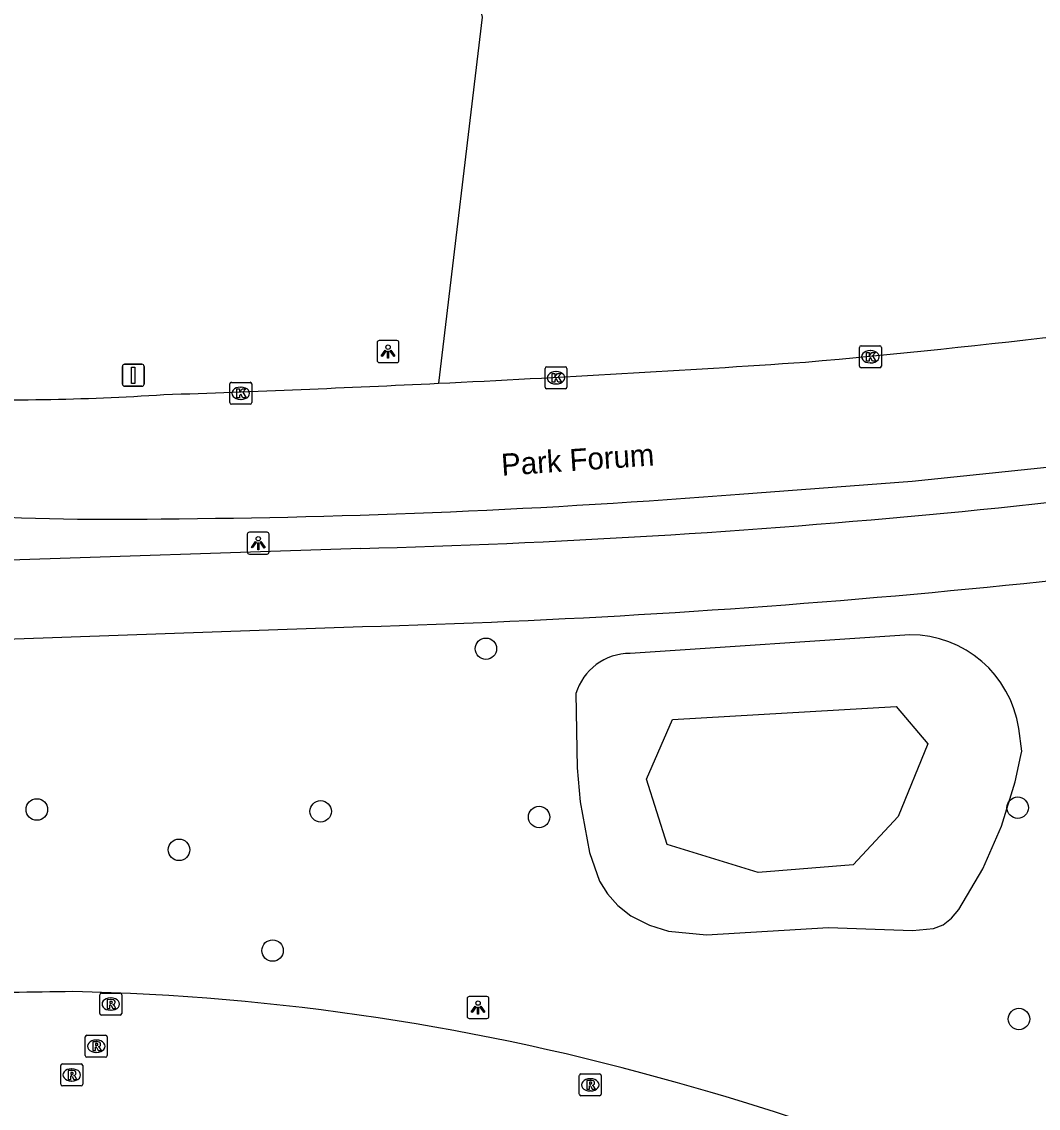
# Model space of a CAD drawing. Extents: x 154324 to 155743, y 382939 to 384183.
# Drawn here: x 155304.56 to 155350.9, y 383470.22 to 383519.75 of the extents above; entities that cross this region are included whole.
import ezdxf

# ---------------------------------------------------------------- set-up
doc = ezdxf.new("R2010")
doc.units = 0
for name, color, linetype in [('IMGEO_Berm_groen', 7, 'Continuous'), ('IMGEO_Boom', 7, 'Continuous'), ('IMGEO_Fietspad_gesloten', 7, 'Continuous'), ('IMGEO_Groenvoorziening', 7, 'Continuous'), ('IMGEO_Kolk', 7, 'Continuous'), ('IMGEO_Lichtpunt', 7, 'Continuous'), ('IMGEO_Meer_plas_ven_vijver', 7, 'Continuous'), ('IMGEO_Openbare_ruimte_label', 7, 'Continuous'), ('IMGEO_Rijbaan_lokaal_gesloten', 7, 'Continuous'), ('IMGEO_Rijbaan_lokaal_open', 7, 'Continuous'), ('IMGEO_Rioolput', 7, 'Continuous'), ('IMGEO_Verkeersbordpaal', 7, 'Continuous')]:
    doc.layers.add(name, color=color, linetype=linetype)

msp = doc.modelspace()

# ---------------------------------------------------------------- linework, layer by layer
at = {"layer": 'IMGEO_Berm_groen'}
msp.add_lwpolyline([(155249.962, 383983.402), (155261.74, 383912.135), (155306.103, 383602.506), (155325.548, 383519.946), (155323.557, 383503.266)], dxfattribs=at)
at = {"layer": 'IMGEO_Boom'}
for centre in [(155325.724, 383491.168), (155305.253, 383483.841), (155318.191, 383483.757), (155349.966, 383483.923), (155328.148, 383483.498), (155311.734, 383482.003), (155315.999, 383477.412), (155350.024, 383474.291)]:
    msp.add_circle(centre, 0.489, dxfattribs=at)
at = {"layer": 'IMGEO_Fietspad_gesloten'}
for points in [[(155320.016, 383495.74), (155302.646, 383495.154), (155298.319, 383495.134), (155298.615, 383497.439)], [(155299.822, 383491.37), (155302.096, 383491.551), (155320.102, 383492.177)]]:
    msp.add_lwpolyline(points, dxfattribs=at)
for centre, radius, start, end in [((155310.263, 383877.333), 381.717, 271.46401, 279.46134), ((155308.945, 383894.859), 402.836, 271.58712, 279.22715)]:
    msp.add_arc(centre, radius, start, end, dxfattribs=at)
at = {"layer": 'IMGEO_Groenvoorziening'}
for points in [[(155345.053, 383491.808), (155332.293, 383490.958)], [(155329.827, 383489.121), (155329.88, 383485.737), (155330.021, 383484.191), (155330.45, 383481.888), (155330.906, 383480.582), (155331.267, 383479.991), (155331.738, 383479.46), (155332.334, 383479.002), (155333.186, 383478.567), (155334.045, 383478.3), (155335.78, 383478.124), (155341.334, 383478.467), (155345.17, 383478.319), (155346.128, 383478.422), (155346.575, 383478.592), (155346.952, 383478.891), (155347.276, 383479.28), (155348.376, 383481.137)], [(155348.376, 383481.137), (155349.221, 383483.087), (155349.842, 383485.097), (155350.114, 383486.303), (155350.16, 383486.506), (155350.011, 383487.539)]]:
    msp.add_lwpolyline(points, dxfattribs=at)
for centre, radius, start, end in [((155345.053, 383486.794), 5.014, 8.5403, 90.0007), ((155332.295, 383488.382), 2.576, 90.0351, 163.332)]:
    msp.add_arc(centre, radius, start, end, dxfattribs=at)
at = {"layer": 'IMGEO_Kolk'}
for p, q in [((155342.749, 383504.05), (155342.749, 383504.902)), ((155342.824, 383504.976), (155343.676, 383504.976)), ((155343.237, 383504.756), (155343.262, 383504.756)), ((155343.75, 383504.902), (155343.75, 383504.05)), ((155328.493, 383504.017), (155329.345, 383504.017)), ((155343.26, 383504.196), (155343.235, 383504.196)), ((155328.418, 383503.091), (155328.418, 383503.943)), ((155328.906, 383503.797), (155328.931, 383503.797)), ((155329.419, 383503.943), (155329.419, 383503.091)), ((155343.676, 383503.976), (155342.824, 383503.976)), ((155314.049, 383502.384), (155314.049, 383503.236)), ((155314.124, 383503.31), (155314.976, 383503.31)), ((155314.537, 383503.09), (155314.562, 383503.09)), ((155315.05, 383503.236), (155315.05, 383502.384)), ((155329.345, 383503.017), (155328.493, 383503.017)), ((155328.929, 383503.237), (155328.904, 383503.237)), ((155314.56, 383502.53), (155314.535, 383502.53)), ((155314.976, 383502.31), (155314.124, 383502.31))]:
    msp.add_line(p, q, dxfattribs=at)
for points in [[(155342.749, 383504.05), (155342.749, 383504.902)], [(155342.824, 383504.976), (155343.676, 383504.976)], [(155343.07, 383504.676), (155343.193, 383504.676), (155343.193, 383504.525), (155343.323, 383504.676), (155343.487, 383504.676), (155343.341, 383504.525), (155343.494, 383504.276), (155343.342, 383504.276), (155343.257, 383504.44), (155343.193, 383504.373), (155343.193, 383504.276), (155343.07, 383504.276), (155343.07, 383504.676)], [(155343.75, 383504.902), (155343.75, 383504.05)], [(155328.493, 383504.017), (155329.345, 383504.017)], [(155328.418, 383503.091), (155328.418, 383503.943)], [(155328.739, 383503.717), (155328.862, 383503.717), (155328.862, 383503.566), (155328.992, 383503.717), (155329.156, 383503.717), (155329.01, 383503.566), (155329.163, 383503.317), (155329.011, 383503.317), (155328.926, 383503.481), (155328.862, 383503.414), (155328.862, 383503.317), (155328.739, 383503.317), (155328.739, 383503.717)], [(155329.419, 383503.943), (155329.419, 383503.091)], [(155343.676, 383503.976), (155342.824, 383503.976)], [(155314.049, 383502.384), (155314.049, 383503.236)], [(155314.124, 383503.31), (155314.976, 383503.31)], [(155315.05, 383503.236), (155315.05, 383502.384)], [(155329.345, 383503.017), (155328.493, 383503.017)], [(155314.37, 383503.01), (155314.493, 383503.01), (155314.493, 383502.859), (155314.623, 383503.01), (155314.787, 383503.01), (155314.641, 383502.859), (155314.794, 383502.61), (155314.642, 383502.61), (155314.557, 383502.774), (155314.493, 383502.707), (155314.493, 383502.61), (155314.37, 383502.61), (155314.37, 383503.01)], [(155314.976, 383502.31), (155314.124, 383502.31)]]:
    msp.add_lwpolyline(points, dxfattribs=at)
for centre, start, end in [((155342.826, 383504.9), 91.552, 178.448), ((155342.826, 383504.9), 91.552, 178.448), ((155343.674, 383504.9), 1.552, 88.448), ((155343.674, 383504.9), 1.552, 88.448), ((155328.495, 383503.941), 91.552, 178.448), ((155328.495, 383503.941), 91.552, 178.448), ((155329.343, 383503.941), 1.552, 88.448), ((155329.343, 383503.941), 1.552, 88.448), ((155342.826, 383504.052), 181.552, 268.448), ((155342.826, 383504.052), 181.552, 268.448), ((155343.674, 383504.052), 271.552, 358.448), ((155343.674, 383504.052), 271.552, 358.448), ((155314.126, 383503.234), 91.552, 178.448), ((155314.126, 383503.234), 91.552, 178.448), ((155314.974, 383503.234), 1.552, 88.448), ((155314.974, 383503.234), 1.552, 88.448), ((155328.495, 383503.093), 181.552, 268.448), ((155328.495, 383503.093), 181.552, 268.448), ((155329.343, 383503.093), 271.552, 358.448), ((155329.343, 383503.093), 271.552, 358.448), ((155314.126, 383502.386), 181.552, 268.448), ((155314.126, 383502.386), 181.552, 268.448), ((155314.974, 383502.386), 271.552, 358.448), ((155314.974, 383502.386), 271.552, 358.448)]:
    msp.add_arc(centre, 0.0765, start, end, dxfattribs=at)
for centre, major_axis, ratio, start_param, end_param in [((155343.236, 383504.476), (-0.387, 0.002), 0.722429, 4.712389, 7.853982), ((155343.261, 383504.476), (-0.39, 0.002), 0.717154, 1.570796, 4.712389), ((155328.905, 383503.517), (-0.387, 0.002), 0.722429, 4.712389, 7.853982), ((155328.93, 383503.517), (-0.39, 0.002), 0.717154, 1.570796, 4.712389), ((155314.536, 383502.81), (-0.387, 0.002), 0.722429, 4.712389, 7.853982), ((155314.561, 383502.81), (-0.39, 0.002), 0.717154, 1.570796, 4.712389)]:
    msp.add_ellipse(centre, major_axis=major_axis, ratio=ratio, start_param=start_param, end_param=end_param, dxfattribs=at)
at = {"layer": 'IMGEO_Lichtpunt'}
for p, q in [((155320.764, 383505.115), (155320.764, 383504.308)), ((155320.764, 383505.115), (155320.764, 383504.308)), ((155321.666, 383505.21), (155320.858, 383505.21)), ((155321.666, 383505.21), (155320.858, 383505.21)), ((155321.76, 383504.308), (155321.76, 383505.115)), ((155321.76, 383504.308), (155321.76, 383505.115)), ((155320.858, 383504.214), (155321.666, 383504.214)), ((155320.858, 383504.214), (155321.666, 383504.214)), ((155314.846, 383496.386), (155314.846, 383495.579)), ((155314.846, 383496.386), (155314.846, 383495.579)), ((155315.748, 383496.481), (155314.94, 383496.481)), ((155315.748, 383496.481), (155314.94, 383496.481)), ((155315.842, 383495.579), (155315.842, 383496.386)), ((155315.842, 383495.579), (155315.842, 383496.386)), ((155314.94, 383495.485), (155315.748, 383495.485)), ((155314.94, 383495.485), (155315.748, 383495.485)), ((155325.769, 383475.313), (155324.961, 383475.313)), ((155325.769, 383475.313), (155324.961, 383475.313)), ((155324.867, 383475.218), (155324.867, 383474.411)), ((155324.867, 383475.218), (155324.867, 383474.411)), ((155325.863, 383474.411), (155325.863, 383475.218)), ((155325.863, 383474.411), (155325.863, 383475.218)), ((155324.961, 383474.317), (155325.769, 383474.317)), ((155324.961, 383474.317), (155325.769, 383474.317))]:
    msp.add_line(p, q, dxfattribs=at)
for points in [[(155321.138, 383504.779), (155321.177, 383504.751), (155320.989, 383504.489), (155320.951, 383504.516), (155321.138, 383504.779)], [(155321.24, 383504.731), (155321.287, 383504.731), (155321.287, 383504.409), (155321.24, 383504.409), (155321.24, 383504.731)], [(155321.35, 383504.751), (155321.388, 383504.778), (155321.575, 383504.516), (155321.536, 383504.488), (155321.35, 383504.751)], [(155315.22, 383496.05), (155315.259, 383496.022), (155315.071, 383495.76), (155315.033, 383495.787), (155315.22, 383496.05)], [(155315.322, 383496.002), (155315.369, 383496.002), (155315.369, 383495.68), (155315.322, 383495.68), (155315.322, 383496.002)], [(155315.432, 383496.022), (155315.47, 383496.049), (155315.657, 383495.787), (155315.618, 383495.759), (155315.432, 383496.022)], [(155325.241, 383474.882), (155325.28, 383474.854), (155325.092, 383474.592), (155325.054, 383474.619), (155325.241, 383474.882)], [(155325.343, 383474.834), (155325.39, 383474.834), (155325.39, 383474.512), (155325.343, 383474.512), (155325.343, 383474.834)], [(155325.453, 383474.854), (155325.491, 383474.881), (155325.678, 383474.619), (155325.639, 383474.591), (155325.453, 383474.854)]]:
    msp.add_lwpolyline(points, dxfattribs=at)
for centre in [(155321.263, 383504.913), (155315.345, 383496.184), (155325.366, 383475.016)]:
    msp.add_circle(centre, 0.0994, dxfattribs=at)
for centre, start, end in [((155320.858, 383505.115), 90, 180), ((155320.858, 383505.115), 90, 180), ((155321.666, 383505.115), 0, 90), ((155321.666, 383505.115), 0, 90), ((155320.858, 383504.308), 180, 270), ((155320.858, 383504.308), 180, 270), ((155321.666, 383504.308), 270, 0), ((155321.666, 383504.308), 270, 360), ((155314.94, 383496.386), 90, 180), ((155314.94, 383496.386), 90, 180), ((155315.748, 383496.386), 0, 90), ((155315.748, 383496.386), 0, 90), ((155314.94, 383495.579), 180, 270), ((155314.94, 383495.579), 180, 270), ((155315.748, 383495.579), 270, 0), ((155315.748, 383495.579), 270, 360), ((155324.961, 383475.218), 90, 180), ((155324.961, 383475.218), 90, 180), ((155325.769, 383475.218), 0, 90), ((155325.769, 383475.218), 0, 90), ((155324.961, 383474.411), 180, 270), ((155324.961, 383474.411), 180, 270), ((155325.769, 383474.411), 270, 0), ((155325.769, 383474.411), 270, 360)]:
    msp.add_arc(centre, 0.0946, start, end, dxfattribs=at)
at = {"layer": 'IMGEO_Meer_plas_ven_vijver'}
msp.add_lwpolyline([(155334.234, 383487.937), (155344.425, 383488.531), (155345.868, 383486.833), (155344.51, 383483.521), (155342.471, 383481.313), (155338.14, 383480.973), (155333.979, 383482.247), (155333.045, 383485.219), (155334.234, 383487.937)], dxfattribs=at)
at = {"layer": 'IMGEO_Rijbaan_lokaal_gesloten'}
msp.add_lwpolyline([(155337.28, 383498.213), (155345.16, 383498.813), (155359.046, 383500.247)], dxfattribs=at)
for centre, radius, start, end in [((155300.959, 383944.166), 441.69, 275.10811, 278.33124), ((155280.817, 384389.613), 887.377, 272.760654, 273.842552), ((155280.737, 384393.015), 890.779, 271.949905, 272.755311), ((155303.956, 383609.192), 106.676, 267.89708, 273.81063), ((155308.546, 383862.423), 365.342, 270.37249, 274.51097), ((155308.661, 383608.169), 111.103, 265.91694, 271.16567)]:
    msp.add_arc(centre, radius, start, end, dxfattribs=at)
at = {"layer": 'IMGEO_Rijbaan_lokaal_open'}
for centre, radius, start, end in [((155309.207, 383252.857), 222.696, 90.5946, 93.46876), ((155304.555, 383366.626), 108.94, 74.06499, 88.76862), ((155312.033, 383388.632), 85.735, 58.41362, 74.83277)]:
    msp.add_arc(centre, radius, start, end, dxfattribs=at)
at = {"layer": 'IMGEO_Rioolput'}
for p, q in [((155308.124, 383474.548), (155308.124, 383475.4)), ((155308.199, 383475.474), (155309.051, 383475.474)), ((155309.125, 383475.4), (155309.125, 383474.548)), ((155308.612, 383475.254), (155308.637, 383475.254)), ((155309.051, 383474.474), (155308.199, 383474.474)), ((155308.635, 383474.694), (155308.61, 383474.694)), ((155307.463, 383472.625), (155307.463, 383473.477)), ((155307.538, 383473.551), (155308.39, 383473.551)), ((155307.951, 383473.331), (155307.976, 383473.331)), ((155308.464, 383473.477), (155308.464, 383472.625)), ((155308.39, 383472.551), (155307.538, 383472.551)), ((155307.974, 383472.771), (155307.949, 383472.771)), ((155306.342, 383471.316), (155306.342, 383472.168)), ((155306.417, 383472.242), (155307.269, 383472.242)), ((155306.83, 383472.022), (155306.855, 383472.022)), ((155307.343, 383472.168), (155307.343, 383471.316)), ((155306.853, 383471.462), (155306.828, 383471.462)), ((155329.982, 383470.866), (155329.982, 383471.718)), ((155330.057, 383471.792), (155330.909, 383471.792)), ((155330.47, 383471.572), (155330.495, 383471.572)), ((155330.983, 383471.718), (155330.983, 383470.866)), ((155307.269, 383471.242), (155306.417, 383471.242)), ((155330.493, 383471.012), (155330.468, 383471.012)), ((155330.909, 383470.792), (155330.057, 383470.792))]:
    msp.add_line(p, q, dxfattribs=at)
for points in [[(155308.124, 383474.548), (155308.124, 383475.4)], [(155308.199, 383475.474), (155309.051, 383475.474)], [(155309.125, 383475.4), (155309.125, 383474.548)], [(155308.713, 383475.172), (155308.461, 383475.174), (155308.461, 383474.774)], [(155308.461, 383474.774), (155308.585, 383474.774), (155308.585, 383474.936), (155308.596, 383474.936)], [(155308.639, 383475.093), (155308.585, 383475.093), (155308.585, 383475.012)], [(155308.585, 383475.012), (155308.637, 383475.012)], [(155308.643, 383474.907), (155308.714, 383474.774), (155308.854, 383474.774), (155308.789, 383474.9)], [(155309.051, 383474.474), (155308.199, 383474.474)], [(155307.463, 383472.625), (155307.463, 383473.477)], [(155307.538, 383473.551), (155308.39, 383473.551)], [(155308.464, 383473.477), (155308.464, 383472.625)], [(155308.052, 383473.249), (155307.8, 383473.251), (155307.8, 383472.851)], [(155307.8, 383472.851), (155307.924, 383472.851), (155307.924, 383473.013), (155307.935, 383473.013)], [(155307.978, 383473.17), (155307.924, 383473.17), (155307.924, 383473.089)], [(155307.924, 383473.089), (155307.976, 383473.089)], [(155307.982, 383472.984), (155308.053, 383472.851), (155308.193, 383472.851), (155308.128, 383472.977)], [(155308.39, 383472.551), (155307.538, 383472.551)], [(155306.342, 383471.316), (155306.342, 383472.168)], [(155306.417, 383472.242), (155307.269, 383472.242)], [(155306.931, 383471.94), (155306.679, 383471.942), (155306.679, 383471.542)], [(155306.857, 383471.861), (155306.803, 383471.861), (155306.803, 383471.78)], [(155307.343, 383472.168), (155307.343, 383471.316)], [(155306.679, 383471.542), (155306.803, 383471.542), (155306.803, 383471.704), (155306.814, 383471.704)], [(155306.803, 383471.78), (155306.855, 383471.78)], [(155306.861, 383471.675), (155306.932, 383471.542), (155307.072, 383471.542), (155307.007, 383471.668)], [(155329.982, 383470.866), (155329.982, 383471.718)], [(155330.057, 383471.792), (155330.909, 383471.792)], [(155330.571, 383471.49), (155330.319, 383471.492), (155330.319, 383471.092)], [(155330.497, 383471.411), (155330.443, 383471.411), (155330.443, 383471.33)], [(155330.443, 383471.33), (155330.495, 383471.33)], [(155330.983, 383471.718), (155330.983, 383470.866)], [(155307.269, 383471.242), (155306.417, 383471.242)], [(155330.319, 383471.092), (155330.443, 383471.092), (155330.443, 383471.254), (155330.454, 383471.254)], [(155330.501, 383471.225), (155330.572, 383471.092), (155330.712, 383471.092), (155330.647, 383471.218)], [(155330.909, 383470.792), (155330.057, 383470.792)]]:
    msp.add_lwpolyline(points, dxfattribs=at)
for centre, radius, start, end in [((155308.201, 383475.398), 0.0765, 91.552, 178.448), ((155308.201, 383475.398), 0.0765, 91.552, 178.448), ((155309.049, 383475.398), 0.0765, 1.552, 88.448), ((155309.049, 383475.398), 0.0765, 1.552, 88.448), ((155308.595, 383474.883), 0.0533, 26.0293, 88.6989), ((155308.621, 383475.201), 0.19, 274.7715, 282.9687), ((155308.645, 383474.997), 0.0964, 77.0061, 93.1865), ((155308.659, 383475.054), 0.0378, 276.6634, 79.6772), ((155308.712, 383475.062), 0.109, 350.3612, 89.416), ((155308.71, 383475.062), 0.112, 277.5842, 350.9817), ((155308.694, 383474.847), 0.108, 29.5134, 73.7905), ((155308.201, 383474.55), 0.0765, 181.552, 268.448), ((155308.201, 383474.55), 0.0765, 181.552, 268.448), ((155309.049, 383474.55), 0.0765, 271.552, 358.448), ((155309.049, 383474.55), 0.0765, 271.552, 358.448), ((155307.54, 383473.475), 0.0765, 91.552, 178.448), ((155307.54, 383473.475), 0.0765, 91.552, 178.448), ((155308.388, 383473.475), 0.0765, 1.552, 88.448), ((155308.388, 383473.475), 0.0765, 1.552, 88.448), ((155307.934, 383472.96), 0.0533, 26.0293, 88.6989), ((155307.96, 383473.278), 0.19, 274.7715, 282.9687), ((155307.984, 383473.074), 0.0964, 77.0061, 93.1865), ((155307.998, 383473.131), 0.0378, 276.6634, 79.6772), ((155308.051, 383473.139), 0.109, 350.3612, 89.416), ((155308.049, 383473.139), 0.112, 277.5842, 350.9817), ((155308.033, 383472.924), 0.108, 29.5134, 73.7905), ((155307.54, 383472.627), 0.0765, 181.552, 268.448), ((155307.54, 383472.627), 0.0765, 181.552, 268.448), ((155308.388, 383472.627), 0.0765, 271.552, 358.448), ((155308.388, 383472.627), 0.0765, 271.552, 358.448), ((155306.419, 383472.166), 0.0765, 91.552, 178.448), ((155306.419, 383472.166), 0.0765, 91.552, 178.448), ((155306.863, 383471.765), 0.0964, 77.0061, 93.1865), ((155306.877, 383471.822), 0.0378, 276.6634, 79.6772), ((155306.93, 383471.83), 0.109, 350.3612, 89.416), ((155307.267, 383472.166), 0.0765, 1.552, 88.448), ((155307.267, 383472.166), 0.0765, 1.552, 88.448), ((155306.813, 383471.651), 0.0533, 26.0293, 88.6989), ((155306.839, 383471.969), 0.19, 274.7715, 282.9687), ((155306.928, 383471.83), 0.112, 277.5842, 350.9817), ((155306.912, 383471.615), 0.108, 29.5134, 73.7905), ((155330.059, 383471.716), 0.0765, 91.552, 178.448), ((155330.059, 383471.716), 0.0765, 91.552, 178.448), ((155330.479, 383471.519), 0.19, 274.7715, 282.9687), ((155330.503, 383471.315), 0.0964, 77.0061, 93.1865), ((155330.517, 383471.372), 0.0378, 276.6634, 79.6772), ((155330.57, 383471.38), 0.109, 350.3612, 89.416), ((155330.568, 383471.38), 0.112, 277.5842, 350.9817), ((155330.907, 383471.716), 0.0765, 1.552, 88.448), ((155330.907, 383471.716), 0.0765, 1.552, 88.448), ((155306.419, 383471.318), 0.0765, 181.552, 268.448), ((155306.419, 383471.318), 0.0765, 181.552, 268.448), ((155307.267, 383471.318), 0.0765, 271.552, 358.448), ((155307.267, 383471.318), 0.0765, 271.552, 358.448), ((155330.059, 383470.868), 0.0765, 181.552, 268.448), ((155330.059, 383470.868), 0.0765, 181.552, 268.448), ((155330.453, 383471.201), 0.0533, 26.0293, 88.6989), ((155330.552, 383471.165), 0.108, 29.5134, 73.7905), ((155330.907, 383470.868), 0.0765, 271.552, 358.448), ((155330.907, 383470.868), 0.0765, 271.552, 358.448)]:
    msp.add_arc(centre, radius, start, end, dxfattribs=at)
for centre, major_axis, ratio, start_param, end_param in [((155308.611, 383474.974), (-0.387, 0.002), 0.722429, 4.712389, 7.853982), ((155308.636, 383474.974), (-0.39, 0.002), 0.717154, 1.570796, 4.712389), ((155307.95, 383473.051), (-0.387, 0.002), 0.722429, 4.712389, 7.853982), ((155307.975, 383473.051), (-0.39, 0.002), 0.717154, 1.570796, 4.712389), ((155306.829, 383471.742), (-0.387, 0.002), 0.722429, 4.712389, 7.853982), ((155306.854, 383471.742), (-0.39, 0.002), 0.717154, 1.570796, 4.712389), ((155330.469, 383471.292), (-0.387, 0.002), 0.722429, 4.712389, 7.853982), ((155330.494, 383471.292), (-0.39, 0.002), 0.717154, 1.570796, 4.712389)]:
    msp.add_ellipse(centre, major_axis=major_axis, ratio=ratio, start_param=start_param, end_param=end_param, dxfattribs=at)
at = {"layer": 'IMGEO_Verkeersbordpaal'}
for p, q in [((155309.154, 383503.232), (155309.154, 383504.032)), ((155309.154, 383504.032), (155309.154, 383503.232)), ((155309.254, 383504.132), (155310.044, 383504.132)), ((155310.044, 383504.132), (155309.254, 383504.132)), ((155310.144, 383504.032), (155310.144, 383503.232)), ((155310.144, 383503.232), (155310.144, 383504.032)), ((155310.044, 383503.132), (155309.254, 383503.132)), ((155309.254, 383503.132), (155310.044, 383503.132))]:
    msp.add_line(p, q, dxfattribs=at)
msp.add_lwpolyline([(155309.574, 383504.007), (155309.724, 383504.007), (155309.724, 383503.257), (155309.574, 383503.257), (155309.574, 383504.007)], dxfattribs=at)
for centre, start, end in [((155309.254, 383504.032), 90, 180), ((155309.254, 383504.032), 90, 180), ((155310.044, 383504.032), 0, 90), ((155310.044, 383504.032), 360, 90), ((155309.254, 383503.232), 180, 270), ((155309.254, 383503.232), 180, 270), ((155310.044, 383503.232), 270, 0), ((155310.044, 383503.232), 270, 0)]:
    msp.add_arc(centre, 0.1, start, end, dxfattribs=at)

# ---------------------------------------------------------------- texts
at = {"layer": 'IMGEO_Openbare_ruimte_label'}
msp.add_text('Park Forum', height=1, rotation=3.8979, dxfattribs=at).set_placement((155326.456, 383499.051))

doc.saveas('drawing.dxf')
